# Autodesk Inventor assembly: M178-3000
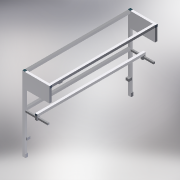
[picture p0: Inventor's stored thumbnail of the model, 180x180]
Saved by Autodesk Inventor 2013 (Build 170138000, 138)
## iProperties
Created: 2004-11
Part Number: M178-3000
Document SubType Name: Assembly
Designer: Autodesk, Inc.
Manufacturer: Standard
Standards Organization: Custom
Mass: 21755.4 g
Surface Area: 53805.6 cm^2
Volume: 7961.36 cm^3
Density: 2.73263 g/cm^3
CAGE: 1LJX3
Dept. ID: Product Design
Description #2: ---
Finish #1: ---
Finish #2: ---
Material ID: ---
Project Number: ---
Author: Autodesk, Inc.
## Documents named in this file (14)
- Z:\_DATEN\Test Station\Components\M178-3000.iam
- Z:\_DATEN\Test Station\Components\M178-3001.ipt
- Z:\_DATEN\Test Station\Components\21-135 Corner Phantom.iam
- Z:\_DATEN\Test Station\Components\21-135 Corner Phantom 2.iam
- Z:\_DATEN\Test Station\Components\M178-3002.ipt
- Z:\_DATEN\Test Station\Components\M178-100_Cross_Phantom.iam
- Z:\_DATEN\Test Station\Components\M178-3000 Overhange Phantom.iam
- Z:\_DATEN\Test Station\Components\22-136.ipt
- Z:\_DATEN\Test Station\Components\22-130.iam
- Z:\_DATEN\Test Station\Components\18-813.ipt
- Z:\_DATEN\Test Station\Components\22-134.iam
- C:\Users\kelleyb.ADS\Desktop\Samples MIGRATED 2009 224 RTM_1\Standard Parts\Test Station Content\Extrusions\40 Series Profiles.ipt
- C:\Users\kelleyb.ADS\Desktop\Samples MIGRATED 2009 224 RTM_1\Standard Parts\Test Station Content\End Caps\18-xxx 40 Series End Caps.ipt
- Z:\_DATEN\Test Station\Components\M178-3000_Ersatzobjekt_1.ipt
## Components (24 placed, 11 different names)
1. M178-3001:1 — Flush:1, Mate:1, Flush:3, Flush:4, Mate:4, Mate:5, Flush:6, Mate:6, Angle:1, Flush:7, Mate:8, Mate:9, Mate:10, Flush:11, Mate:13, Flush:12, Flush:13, Mate:14, Flush:14, Flush:15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
2. M178-3001:2 — Mate:1, Flush:3, Flush:4, Mate:7, Flush:9
3. 21-135 Corner Phantom:1 [sub-assembly] — Mate:6, Angle:1, Flush:7, Flush:10
4. 21-135 Corner Phantom:2 [sub-assembly] — Mate:7, Flush:9, Flush:10
5. M178-3002:3 — Mate:11, Flush:11, Mate:12, Insert:4, Angle:4, Insert:5, Angle:5
6. M178-100_Cross_Phantom:3 [sub-assembly] — Mate:15, Flush:16, Flush:17, Mate:16, Flush:18
7. 22-136:1 — Mate:16, Flush:18
8. 18-813:5 — Insert:4, Angle:4
9. 18-813:6 — Insert:5, Angle:5
10. M178-3000_Ersatzobjekt_1:1
11. 22-130:1 [sub-assembly] — Mate:8, Mate:9, Mate:10, Insert:1
12. 22-134:1 [sub-assembly] — Mate:11, Mate:12, Insert:1
13. 22-130:2 [sub-assembly]
14. 22-134:2 [sub-assembly]
15. 21-135 Corner Phantom 2:1 [sub-assembly] — Mate:4, Mate:5, Flush:6
16. 21-135 Corner Phantom 2:2 [sub-assembly]
17. M178-100_Cross_Phantom:1 [sub-assembly] — Mate:13, Flush:12, Flush:13
18. M178-100_Cross_Phantom:2 [sub-assembly]
19. M178-3000 Overhange Phantom:1 [sub-assembly] — Mate:14, Flush:14, Flush:15, Mate:15, Flush:16, Flush:17, Insert:3, Angle:2
20. 18-813:1 — Insert:2, Angle:3
21. 18-813:2 — Insert:3, Angle:2
22. M178-3000 Overhange Phantom:2 [sub-assembly]
23. 18-813:7
24. 18-813:8
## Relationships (39: Flush 15, Mate 14, Angle 5, Insert 5)
- Flush:1: M178-3001:1
- Mate:1: M178-3001:1 ↔ M178-3001:2
- Flush:3: M178-3001:1 ↔ M178-3001:2
- Flush:4: M178-3001:1 ↔ M178-3001:2
- Mate:4: M178-3001:1 ↔ 21-135 Corner Phantom 2:1
- Mate:5: M178-3001:1 ↔ 21-135 Corner Phantom 2:1
- Flush:6: M178-3001:1 ↔ 21-135 Corner Phantom 2:1
- Mate:6: M178-3001:1 ↔ 21-135 Corner Phantom:1
- Angle:1: M178-3001:1 ↔ 21-135 Corner Phantom:1
- Flush:7: M178-3001:1 ↔ 21-135 Corner Phantom:1
- Mate:7: M178-3001:2 ↔ 21-135 Corner Phantom:2
- Flush:9: M178-3001:2 ↔ 21-135 Corner Phantom:2
- Flush:10: 21-135 Corner Phantom:1 ↔ 21-135 Corner Phantom:2
- Mate:8: M178-3001:1 ↔ 22-130:1
- Mate:9: M178-3001:1 ↔ 22-130:1
- Mate:10: M178-3001:1 ↔ 22-130:1
- Mate:11: M178-3002:3 ↔ 22-134:1
- Flush:11: M178-3001:1 ↔ M178-3002:3
- Mate:12: M178-3002:3 ↔ 22-134:1
- Mate:13: M178-3001:1 ↔ M178-100_Cross_Phantom:1
- Flush:12: M178-3001:1 ↔ M178-100_Cross_Phantom:1
- Flush:13: M178-3001:1 ↔ M178-100_Cross_Phantom:1
- Insert:1: 22-130:1 ↔ 22-134:1
- Mate:14: M178-3001:1 ↔ M178-3000 Overhange Phantom:1
- Flush:14: M178-3001:1 ↔ M178-3000 Overhange Phantom:1
- Flush:15: M178-3001:1 ↔ M178-3000 Overhange Phantom:1
- Mate:15: M178-100_Cross_Phantom:3 ↔ M178-3000 Overhange Phantom:1
- Flush:16: M178-100_Cross_Phantom:3 ↔ M178-3000 Overhange Phantom:1
- Flush:17: M178-100_Cross_Phantom:3 ↔ M178-3000 Overhange Phantom:1
- Mate:16: M178-100_Cross_Phantom:3 ↔ 22-136:1
- Flush:18: M178-100_Cross_Phantom:3 ↔ 22-136:1
- Insert:2: M178-3001:1 ↔ 18-813:1
- Insert:3: M178-3000 Overhange Phantom:1 ↔ 18-813:2
- Angle:2: M178-3000 Overhange Phantom:1 ↔ 18-813:2
- Angle:3: M178-3001:1 ↔ 18-813:1
- Insert:4: M178-3002:3 ↔ 18-813:5
- Angle:4: M178-3002:3 ↔ 18-813:5
- Insert:5: M178-3002:3 ↔ 18-813:6
- Angle:5: M178-3002:3 ↔ 18-813:6
